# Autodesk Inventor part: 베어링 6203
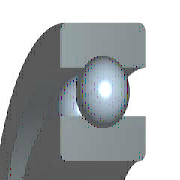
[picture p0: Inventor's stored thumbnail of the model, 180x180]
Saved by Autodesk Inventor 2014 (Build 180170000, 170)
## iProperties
IsCustomPart: 0
Created: 2018-09
Part Number: 베어링 6203
Material: 스테인리스강
Description: 깊은 그루브 볼 베어링
Document SubType Name: Modeling
Standard: KS B 2023
Standards Organization: KS
Language: ko-KR
Size Designation: 6203 - 17 x 40 x 12
Categories: <MemberInstance><Categories><Category DisplayName="샤프트 부품" InternalName="7f7aeb1f-a693-4053-b835-cee3144e0d98" Mnemonic="SHFT"><Category DisplayName="베어링" Inter
Density: 8.08 g/cm^3
Mass: 66.7997 g
Surface Area: 64.3582 cm^2
Volume: 8.26729 cm^3
Appearance: 보라색
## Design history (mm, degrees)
sketch "스케치" dims "d0" = 5.98 (= -0.26 x WD + 0.26 x BD)
  geometry: L1 (3.01, 14.25)-(8.99, 14.25); L2 (6, 14.25)-(6, 11.26); L3 (6, 14.25)-(6, 17.24); L4 (3.778, 12.249)-(0, 12.249); L5 (0, 8.5)-(12, 8.5); L6 (3.778, 16.251)-(0, 16.251); L7 (0, 20)-(12, 20); L8 (12, 8.5)-(12, 12.249); L9 (8.222, 12.249)-(12, 12.249); L10 (8.222, 16.251)-(12, 16.251); L11 (12, 20)-(12, 16.251); L12 (-1.4, 0)-(8.4, 0) reference; L13 (0, -0.3)-(0, 5.3) reference
  constraints: 22 end point, 4 point on line, 2 collinear, 2 perpendicular, 2 symmetric about line, 1 midpoint, 1 parallel, 14 other
  dimensions: "d9" = 17 diameter of L5 L12 (= WD); "d11" = 40 diameter of L7 L12 (= BD); "d12" = 12 distance between parallel lines of L8 L13 (= KB); "d13" = 24.498 diameter of L9 L12 (= 0.326 x BD + 0.674 x WD)
revolve "본체" stored, may be unused: angle "d6" = 90 deg
revolve "볼" stored, may be unused: angle "d7" = 90 deg
pattern_circular "IDS_ARRAYBALL[SIMPL:T]" dims angle "d3" = 360 deg
body "Solid1"
fillet "모깎기1" dims "d1" = 0.6 (= KRS)
other parameters: "WD" = 17 [user parameter; used in 5 equation terms], "BD" = 40 [user parameter; used in 5 equation terms], "KB" = 12 [user parameter; used in 1 equation term], "KRS" = 0.6 [user parameter; used in 1 equation term], "d4" = 0, "d5" = 0, "d8" = 0, "d14" = 0, "d15" = 0, "BBA" = 0 [user parameter], "BC0" = 4750000 [user parameter], "BC" = 9560000 [user parameter], "WR" = 8.5 (= 0.5 x WD) [user parameter]
